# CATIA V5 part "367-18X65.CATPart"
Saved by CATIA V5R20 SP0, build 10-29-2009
Part number: 367-18X65
Definition: NONE
Nomenclature: 367-18X65
Source: Unknown
Description: 367-18X65
Bounding box of the stored display mesh (mm): x 0 to 65, y -14 to 14, z -14 to 14
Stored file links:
  C:\Users\Utente\Desktop\IO LAVORO\3D X SITO CF\X SITO\PLASTICA\3D files 367\367-18X65.CATPart
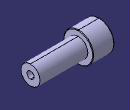
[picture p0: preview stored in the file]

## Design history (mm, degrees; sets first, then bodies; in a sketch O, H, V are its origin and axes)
Body1 "367-18X65" (main body)
  Solid1: solid without history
